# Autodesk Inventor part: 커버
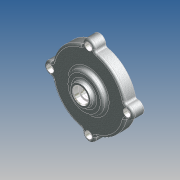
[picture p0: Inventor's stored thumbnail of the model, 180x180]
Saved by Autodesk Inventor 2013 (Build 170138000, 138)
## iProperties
Company: 한국ATC센터
Created: 2014-07
Part Number: 커버
Document SubType Name: 모델링
Designer: KYOUNG IL JANG
Material: Generic
Mass: 72.5678 g
Surface Area: 278.607 cm^2
Volume: 72.5678 cm^3
Density: 1 g/cm^3
변환 표준: STEP AP214IS
파일 이름: C:\Users\SeoGD\Desktop\?쒗뿕\而ㅻ쾭-1.stp
전처리기: Build: 253, Release: 2010 SP1 - Date: Wed 07/29/2009
전송 단위: 밀리미터
불확실성: 0.01
Author: KYOUNG IL JANG
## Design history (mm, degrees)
revolve "회전1" stored, may be unused: angle "d27" = 90 deg
sketch "스케치2" dims "d29" = 104
  geometry: A1 r 8.5 centre (0, 52) between (8.074, 49.344) and (-8.074, 49.344); A2 r 50 centre (0, 0) between (-8.074, 49.344) and (8.074, 49.344) reference; 2 further points
  constraints: 4 point on circle, 2 vertical alignment, 1 centre point, 1 coincident, 2 other
  dimensions: "d28" = 17 diameter of A1
extrude "돌출1" join sketch "스케치2" stored distance "d30" = 10; taper "d31" = 0 deg
fillet "모깎기3" dims "d32" = 3
fillet "모깎기4" dims "d45" = 3, "d46" = 0.2
chamfer "모따기1" distance "d47" = 1; stored, may be unused: second distance "d48" = 2, angle "d49" = 45 deg
hole "구멍2" diameter "d38" = 5.5; stored, may be unused: countersink angle "d42" = 90 deg, drill point angle "d44" = 118 deg; dims "d36" = 10, "d37" = 10, "d39" = 6, "d40" = 9.5, "d41" = 5.4, "d43" = 8
node "솔리드1"
node "솔리드 본체"
node "곡면 본체"
pattern_circular "원형 패턴1" dims angle "d34" = 360 deg
pattern_circular "원형 패턴2" dims angle "d52" = 360 deg
sketch "스케치1"
  geometry: L1 (0, 0)-(0, 26); L2 (50, 0)-(50, 15); L3 (50, 15)-(25, 15); L4 (25, 15)-(25, 21); L5 (25, 21)-(15, 21); L6 (15, 21)-(13.66, 26); L7 (13.66, 26)-(10, 26); L8 (50, 0)-(45, 0); L9 (45, 0)-(45, 10); L10 (45, 10)-(14.5, 10); L11 (14.5, 10)-(13.266, 3); L12 (13.266, 3)-(11, 3); L13 (11, 3)-(11, 16); L14 (11, 16)-(7.5, 16); L15 (7.5, 16)-(7.5, 19); L16 (7.5, 19)-(10, 19); L17 (10, 19)-(10, 26)
  constraints: 34 end point, 10 parallel, 2 perpendicular, 2 point on line, 1 vertical
  dimensions: "d11" = 100 diameter of L2 L1; "d12" = 22 diameter of L13 L1; "d13" = 90 diameter of L9 L1; "d14" = 15 distance between parallel lines of L3 L8; "d15" = 10 distance between parallel lines of L8 L10; "d16" = 29 diameter of L10.end L1; "d17" = 100 deg angle of L11 L10; "d18" = 7 distance between parallel lines of L12 L10; "d19" = 13 distance between parallel lines of L14 L12; "d20" = 3 distance between parallel lines of L16 L14; "d21" = 15 diameter of L15 L1; "d22" = 20 diameter of L17 L1; "d23" = 30 diameter of L5.end L1; "d24" = 6 distance between parallel lines of L5 L3; "d25" = 50 diameter of L4 L1; "d26" = 105 deg angle of L5 L6; "d50" = 26 distance of L1.start L1.end
node "솔리드2"
